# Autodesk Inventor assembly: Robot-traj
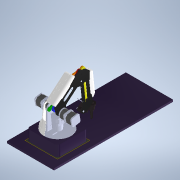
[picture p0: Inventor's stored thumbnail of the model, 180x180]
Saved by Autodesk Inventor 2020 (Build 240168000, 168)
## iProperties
Created: 2017-09
Part Number: Robot-traj
Document SubType Name: Assembly
Designer: bruno
Sending System: SolidWorks 2016
Last Author: Prof
Last Saved: 2018-10-31
Author: bruno
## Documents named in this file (11)
- C:\Users\bruno\Documents\1-Cours-2023-24\1SI\Robot-Dobot\Robot-traj\Robot-traj.iam
- C:\Users\bruno\Documents\1-Cours-2023-24\1SI\Robot-Dobot\Robot-traj\base^robot.iam
- C:\Users\bruno\Documents\1-Cours-2023-24\1SI\Robot-Dobot\Robot-traj\plateforme^robot.iam
- C:\Users\bruno\Documents\1-Cours-2023-24\1SI\Robot-Dobot\Robot-traj\bras inférieur^robot.iam
- C:\Users\bruno\Documents\1-Cours-2023-24\1SI\Robot-Dobot\Robot-traj\manivelle inférieure^robot.iam
- C:\Users\bruno\Documents\1-Cours-2023-24\1SI\Robot-Dobot\Robot-traj\biellette gauche^robot.iam
- C:\Users\bruno\Documents\1-Cours-2023-24\1SI\Robot-Dobot\Robot-traj\biellette droite^robot.iam
- C:\Users\bruno\Documents\1-Cours-2023-24\1SI\Robot-Dobot\Robot-traj\bras supérieur^robot.iam
- C:\Users\bruno\Documents\1-Cours-2023-24\1SI\Robot-Dobot\Robot-traj\basculeur^robot.iam
- C:\Users\bruno\Documents\1-Cours-2023-24\1SI\Robot-Dobot\Robot-traj\biellette avant^robot.iam
- C:\Users\bruno\Documents\1-Cours-2023-24\1SI\Robot-Dobot\Robot-traj\Stylo.iam
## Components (10 placed, 10 different names)
1. base:1 [sub-assembly] — Placage:4, Affleurement:1, Angle:1
2. plateforme:1 [sub-assembly] — Placage:3, Placage:4, Affleurement:1, Placage:5, Placage:6, Placage:7, Placage:8
3. bras inférieur:1 [sub-assembly] — Placage:7, Placage:8, Placage:9, Placage:10, Angle:1
4. manivelle inférieure:1 [sub-assembly] — Placage:1, Placage:2, Placage:3
5. biellette gauche:1 [sub-assembly] — Placage:5, Placage:6, Placage:11, Placage:16
6. biellette droite:1 [sub-assembly] — Placage:1, Placage:2, Placage:20, Placage:21
7. bras supérieur:1 [sub-assembly] — Placage:9, Placage:10, Placage:12, Placage:17, Placage:19, Placage:20, Placage:21
8. basculeur:1 [sub-assembly] — Placage:11, Placage:12, Placage:13, Placage:14, Placage:16
9. biellette avant:1 [sub-assembly] — Placage:13, Placage:14, Placage:18
10. Stylo:1 [sub-assembly] — Placage:17, Placage:18, Placage:19
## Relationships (22: Mate 20, Flush 1, Angle 1)
- Placage:1 [Mate]: manivelle inférieure:1 ↔ biellette droite:1
- Placage:2 [Mate]: manivelle inférieure:1 ↔ biellette droite:1
- Placage:3 [Mate]: plateforme:1 ↔ manivelle inférieure:1
- Placage:4 [Mate]: base:1 ↔ plateforme:1
- Affleurement:1 [Flush]: base:1 ↔ plateforme:1
- Placage:5 [Mate]: plateforme:1 ↔ biellette gauche:1
- Placage:6 [Mate]: plateforme:1 ↔ biellette gauche:1
- Placage:7 [Mate]: plateforme:1 ↔ bras inférieur:1
- Placage:8 [Mate]: plateforme:1 ↔ bras inférieur:1
- Placage:9 [Mate]: bras inférieur:1 ↔ bras supérieur:1
- Placage:10 [Mate]: bras inférieur:1 ↔ bras supérieur:1
- Placage:11 [Mate]: biellette gauche:1 ↔ basculeur:1
- Placage:12 [Mate]: bras supérieur:1 ↔ basculeur:1
- Placage:13 [Mate]: basculeur:1 ↔ biellette avant:1
- Placage:14 [Mate]: basculeur:1 ↔ biellette avant:1
- Placage:16 [Mate]: biellette gauche:1 ↔ basculeur:1
- Placage:17 [Mate]: bras supérieur:1 ↔ Stylo:1
- Placage:18 [Mate]: biellette avant:1 ↔ Stylo:1
- Placage:19 [Mate]: bras supérieur:1 ↔ Stylo:1
- Placage:20 [Mate]: biellette droite:1 ↔ bras supérieur:1
- Placage:21 [Mate]: biellette droite:1 ↔ bras supérieur:1
- Angle:1: base:1 ↔ bras inférieur:1
